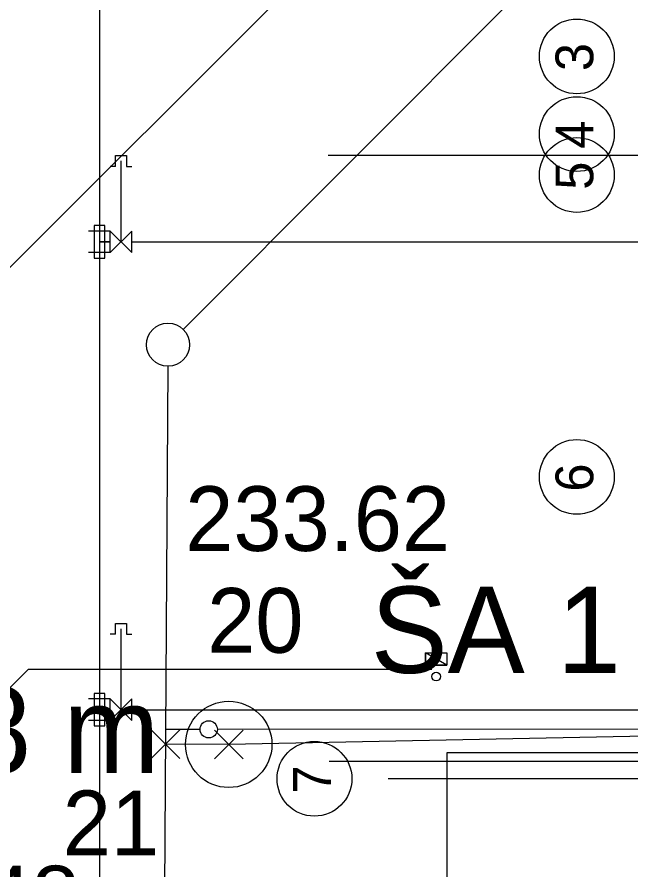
# Model space of a CAD drawing. Extents: x -264031 to -263588, y -1242281 to -1242059.
# Drawn here: x -263926.05 to -263911.83, y -1242121 to -1242101.22 of the extents above; entities that cross this region are included whole.
import ezdxf

# ---------------------------------------------------------------- set-up
doc = ezdxf.new("R2010")
doc.units = 0
for name, color, linetype in [('HESCON_OSI_STAVBY_KFA', 7, 'Continuous'), ('KFA_2D_SITUACIA_DSP', 7, 'Continuous'), ('KFA_BODY_CISLO', 7, 'Continuous'), ('KFA_BODY_SYMBOL', 7, 'Continuous'), ('KFA_BODY_VYSKA', 7, 'Continuous'), ('KFA_JESTV_IS_DSP_-_KANAL_SPLASK', 7, 'Continuous'), ('KFA_SO-40-1-II_SK_MER_TRIBUNA_A', 7, 'Continuous'), ('POPIS', 7, 'Continuous')]:
    doc.layers.add(name, color=color, linetype=linetype)

msp = doc.modelspace()

# ---------------------------------------------------------------- linework, layer by layer
at = {"layer": 'HESCON_OSI_STAVBY_KFA'}
msp.add_line((-263792.653, -1242118.882), (-263917.453, -1242118.882), dxfattribs=at)
for centre in [(-263913.085, -1242102.133), (-263913.085, -1242103.933), (-263913.085, -1242104.883), (-263913.085, -1242111.883), (-263919.163, -1242118.883)]:
    msp.add_circle(centre, 0.867, dxfattribs=at)
at = {"layer": 'KFA_2D_SITUACIA_DSP'}
for p, q in [((-263924.143, -1242082.64), (-263924.143, -1242185.14)), ((-263916.414, -1242097.223), (-263926.239, -1242107.049)), ((-263923.768, -1242104.682), (-263923.768, -1242104.432)), ((-263923.768, -1242104.432), (-263923.518, -1242104.432)), ((-263923.518, -1242104.432), (-263923.518, -1242104.682)), ((-263908.718, -1242104.427), (-263918.846, -1242104.427)), ((-263923.768, -1242104.682), (-263923.893, -1242104.682)), ((-263923.643, -1242106.432), (-263923.643, -1242104.557)), ((-263923.518, -1242104.682), (-263923.393, -1242104.682)), ((-263924.018, -1242106.057), (-263924.268, -1242106.057)), ((-263924.268, -1242106.057), (-263924.268, -1242106.807)), ((-263924.018, -1242106.807), (-263924.018, -1242106.057)), ((-263923.893, -1242106.182), (-263924.393, -1242106.182)), ((-263923.893, -1242106.682), (-263923.893, -1242106.182)), ((-263923.893, -1242106.182), (-263923.393, -1242106.682)), ((-263923.393, -1242106.182), (-263923.893, -1242106.682)), ((-263923.393, -1242106.682), (-263923.393, -1242106.182)), ((-263924.143, -1242106.432), (-263923.893, -1242106.432)), ((-263923.893, -1242106.432), (-263924.143, -1242106.432)), ((-263923.393, -1242106.432), (-263903.343, -1242106.432)), ((-263923.893, -1242106.682), (-263924.393, -1242106.682)), ((-263924.268, -1242106.807), (-263924.018, -1242106.807)), ((-263923.768, -1242115.532), (-263923.768, -1242115.282)), ((-263923.768, -1242115.282), (-263923.518, -1242115.282)), ((-263923.518, -1242115.282), (-263923.518, -1242115.532)), ((-263923.768, -1242115.532), (-263923.893, -1242115.532)), ((-263923.643, -1242117.282), (-263923.643, -1242115.407)), ((-263923.518, -1242115.532), (-263923.393, -1242115.532)), ((-263916.593, -1242116.252), (-263916.593, -1242115.962)), ((-263916.593, -1242115.962), (-263916.093, -1242115.962)), ((-263916.093, -1242116.252), (-263916.593, -1242115.962)), ((-263916.093, -1242116.252), (-263916.593, -1242115.962)), ((-263916.593, -1242115.962), (-263916.593, -1242116.252)), ((-263916.093, -1242115.962), (-263916.093, -1242116.252)), ((-263925.797, -1242116.352), (-263926.592, -1242117.147)), ((-263916.443, -1242116.352), (-263925.797, -1242116.352)), ((-263916.093, -1242116.252), (-263916.593, -1242116.252)), ((-263916.593, -1242116.252), (-263916.093, -1242116.252)), ((-263924.018, -1242116.907), (-263924.268, -1242116.907)), ((-263924.268, -1242116.907), (-263924.268, -1242117.657)), ((-263924.018, -1242117.657), (-263924.018, -1242116.907)), ((-263923.893, -1242117.032), (-263924.393, -1242117.032)), ((-263923.893, -1242117.532), (-263923.893, -1242117.032)), ((-263923.893, -1242117.032), (-263923.393, -1242117.532)), ((-263923.393, -1242117.032), (-263923.893, -1242117.532)), ((-263923.393, -1242117.532), (-263923.393, -1242117.032)), ((-263924.143, -1242117.282), (-263923.893, -1242117.282)), ((-263923.893, -1242117.282), (-263924.143, -1242117.282)), ((-263923.393, -1242117.282), (-263906.493, -1242117.282)), ((-263923.893, -1242117.532), (-263924.393, -1242117.532)), ((-263924.268, -1242117.657), (-263924.018, -1242117.657)), ((-263921.812, -1242117.737), (-263922.612, -1242117.737)), ((-263903.343, -1242117.732), (-263921.412, -1242117.737)), ((-263908.718, -1242118.482), (-263918.819, -1242118.482))]:
    msp.add_line(p, q, dxfattribs=at)
msp.add_lwpolyline([(-263893.618, -1242118.282), (-263916.093, -1242118.282), (-263916.093, -1242175.482), (-263914.293, -1242175.482), (-263914.293, -1242210.482), (-263893.618, -1242210.482), (-263893.618, -1242166.382), (-263900.043, -1242166.382), (-263900.043, -1242162.382), (-263893.618, -1242162.382)], close=True, dxfattribs=at)
for centre, radius in [((-263916.343, -1242116.514), 0.1), ((-263921.612, -1242117.737), 0.2)]:
    msp.add_circle(centre, radius, dxfattribs=at)
at = {"layer": 'KFA_BODY_SYMBOL'}
for p, q in [((-263922.946, -1242118.413), (-263922.283, -1242117.749)), ((-263922.283, -1242118.413), (-263922.946, -1242117.749)), ((-263921.48, -1242118.417), (-263920.817, -1242117.755)), ((-263920.817, -1242118.417), (-263921.48, -1242117.755))]:
    msp.add_line(p, q, dxfattribs=at)
at = {"layer": 'KFA_JESTV_IS_DSP_-_KANAL_SPLASK'}
for p, q in [((-263897.853, -1242084.022), (-263922.202, -1242108.463)), ((-263922.558, -1242109.317), (-263922.76, -1242140.975))]:
    msp.add_line(p, q, dxfattribs=at)
msp.add_circle((-263922.555, -1242108.817), 0.5, dxfattribs=at)
at = {"layer": 'KFA_SO-40-1-II_SK_MER_TRIBUNA_A'}
msp.add_lwpolyline([(-263903.343, -1242117.732), (-263921.148, -1242118.086), (-263922.614, -1242118.081)], dxfattribs=at)
msp.add_circle((-263921.148, -1242118.086), 1, dxfattribs=at)

# ---------------------------------------------------------------- texts
at = {"layer": 'HESCON_OSI_STAVBY_KFA'}
for s, p in [('3', (-263912.704, -1242102.473)), ('4', (-263912.704, -1242104.273)), ('5', (-263912.704, -1242105.223)), ('6', (-263912.704, -1242112.223)), ('7', (-263918.782, -1242119.223))]:
    msp.add_text(s, height=0.875, rotation=90, dxfattribs=at).set_placement(p)
at = {"layer": 'KFA_BODY_CISLO'}
for s, p in [('20', (-263921.648, -1242115.96)), ('21', (-263924.993, -1242120.655))]:
    msp.add_text(s, height=1.5, dxfattribs=at).set_placement(p)
at = {"layer": 'KFA_BODY_VYSKA'}
for s, p in [('233.62', (-263922.155, -1242113.6)), ('233.48', (-263930.734, -1242122.4))]:
    msp.add_text(s, height=1.5, dxfattribs=at).set_placement(p)
at = {"layer": 'POPIS'}
for s, p in [('ŠA 1', (-263917.86, -1242116.428)), ('KA1, DN150 - 19,28 m', (-263949.659, -1242118.748))]:
    msp.add_text(s, height=2, dxfattribs=at).set_placement(p)

doc.saveas('drawing.dxf')
